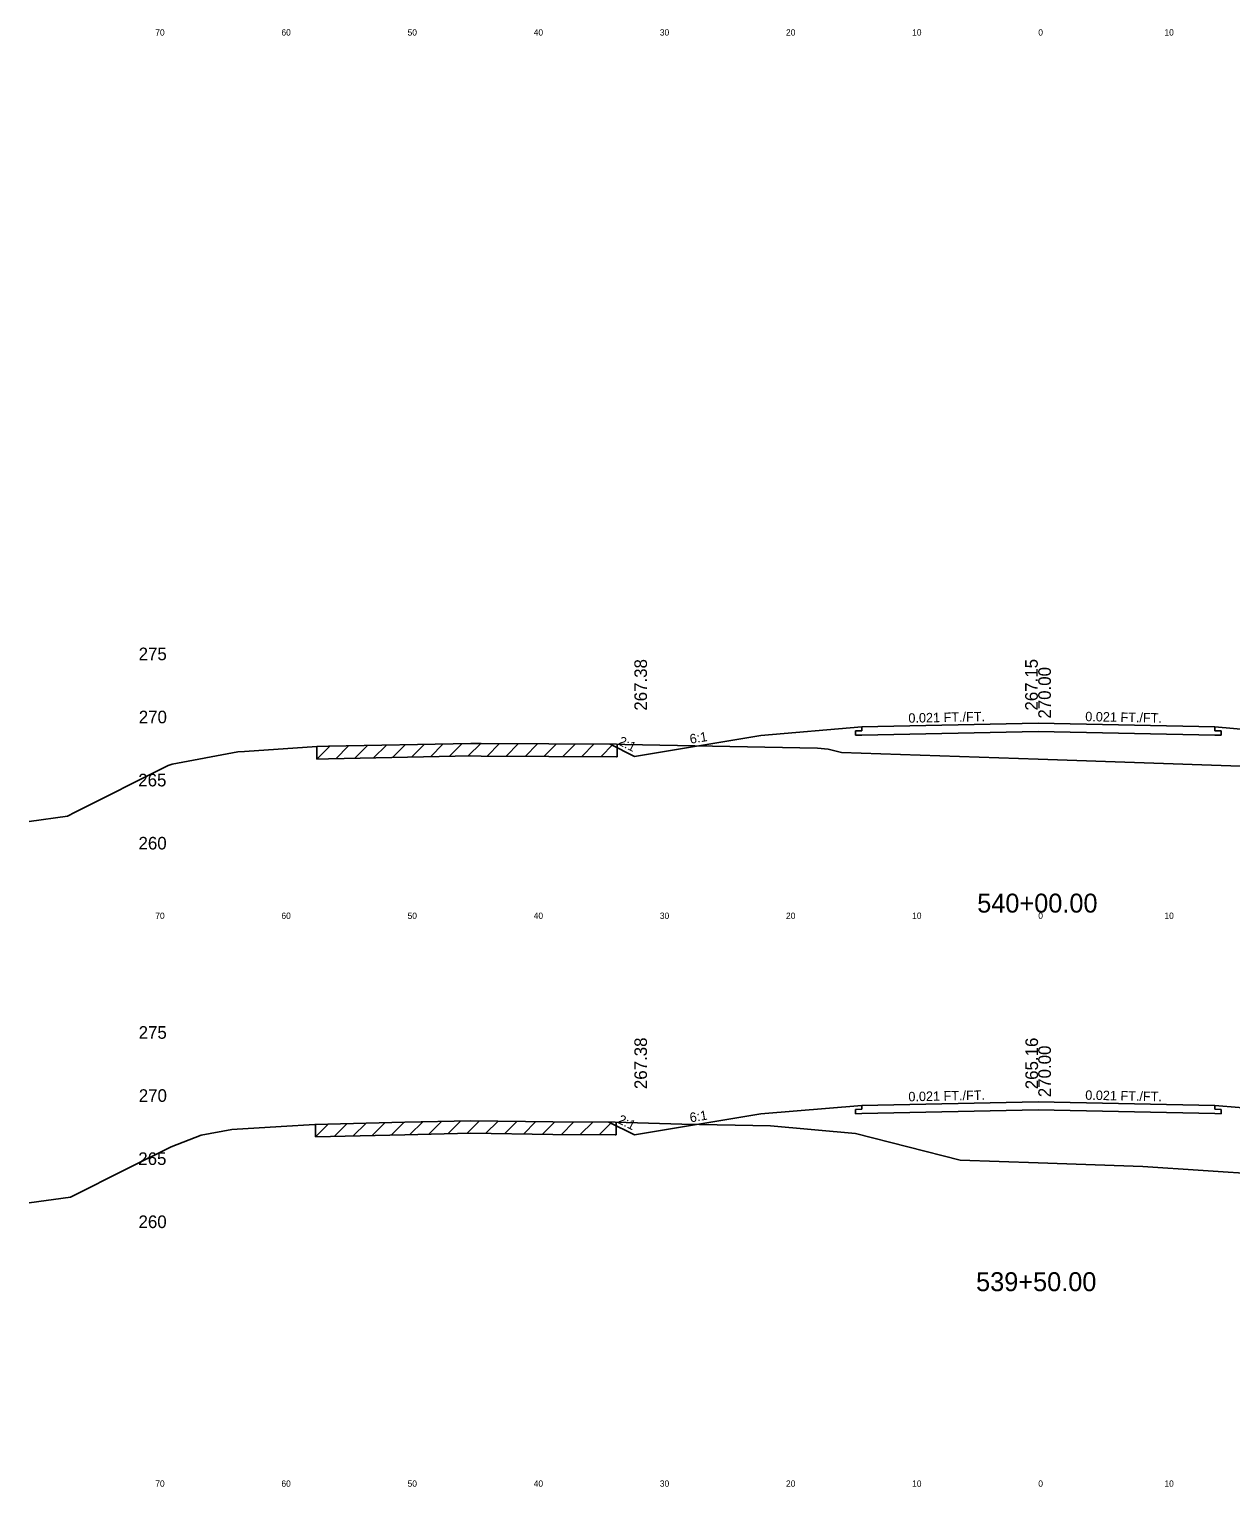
# Model space of a CAD drawing. Extents: x 1000 to 1162, y 999 to 8520.
# Drawn here: x 1000 to 1095.3, y 6059.5 to 6175 of the extents above; entities that cross this region are included whole.
import ezdxf

# ---------------------------------------------------------------- set-up
doc = ezdxf.new("R2010")
doc.units = 0
for name, color, linetype in [('Level 10', 7, 'Continuous'), ('Level 11', 7, 'Continuous'), ('Level 12', 7, 'Continuous'), ('Level 3', 7, 'Continuous'), ('Level 32', 7, 'Continuous'), ('Level 33', 7, 'Continuous'), ('Level 56', 7, 'Continuous'), ('Level 59', 7, 'Continuous'), ('Level 6', 7, 'Continuous'), ('Level 60', 7, 'Continuous'), ('Level 61', 7, 'Continuous'), ('Level 7', 7, 'Continuous')]:
    doc.layers.add(name, color=color, linetype=linetype)

msp = doc.modelspace()

# ---------------------------------------------------------------- linework, layer by layer
at = {"layer": 'Level 11'}
for p, q in [((1066, 6119.41), (1065.5, 6119.4)), ((1065.5, 6119.4), (1065.5, 6119.06)), ((1065.5, 6119.06), (1066, 6119.07)), ((1066, 6119.71), (1066, 6119.41)), ((1094, 6119.41), (1094, 6119.71)), ((1094.5, 6119.4), (1094, 6119.41)), ((1094, 6119.07), (1094.5, 6119.06)), ((1094.5, 6119.06), (1094.5, 6119.4)), ((1066, 6089.41), (1065.5, 6089.4)), ((1065.5, 6089.4), (1065.5, 6089.06)), ((1065.5, 6089.06), (1066, 6089.07)), ((1066, 6089.71), (1066, 6089.41)), ((1094, 6089.41), (1094, 6089.71)), ((1094.5, 6089.4), (1094, 6089.41)), ((1094, 6089.07), (1094.5, 6089.06)), ((1094.5, 6089.06), (1094.5, 6089.4))]:
    msp.add_line(p, q, dxfattribs=at)
at = {"layer": 'Level 12'}
for p, q in [((1080, 6119.36), (1066, 6119.07)), ((1094, 6119.07), (1080, 6119.36)), ((1080, 6089.36), (1066, 6089.07)), ((1094, 6089.07), (1080, 6089.36))]:
    msp.add_line(p, q, dxfattribs=at)
at = {"layer": 'Level 59'}
for p, q in [((1066, 6119.71), (1080, 6120)), ((1080, 6120), (1094, 6119.71)), ((1066, 6089.71), (1080, 6090)), ((1080, 6090), (1094, 6089.71))]:
    msp.add_line(p, q, dxfattribs=at)
at = {"layer": 'Level 6'}
for p, q in [((1058, 6119.04), (1066, 6119.71)), ((1094, 6119.71), (1102, 6119.04)), ((1058, 6089.04), (1066, 6089.71)), ((1094, 6089.71), (1102, 6089.04))]:
    msp.add_line(p, q, dxfattribs=at)
at = {"layer": 'Level 60'}
for p, q in [((1011.35, 6116.77), (1016.55, 6117.74)), ((1016.55, 6117.74), (1017.06, 6117.77)), ((1017.06, 6117.77), (1022.8, 6118.16)), ((1022.8, 6118.16), (1023.72, 6118.18)), ((1023.72, 6118.18), (1035.02, 6118.41)), ((1035.02, 6118.41), (1035.84, 6118.4)), ((1035.84, 6118.4), (1046.56, 6118.35)), ((1046.56, 6118.35), (1047.23, 6118.33)), ((1047.23, 6118.33), (1062.49, 6118.03)), ((1062.49, 6118.03), (1063.34, 6117.95)), ((1063.34, 6117.95), (1064.39, 6117.68)), ((1064.39, 6117.68), (1080, 6117.15)), ((1003.66, 6112.96), (1011.03, 6116.65)), ((1011.03, 6116.65), (1011.35, 6116.77)), ((1080, 6117.15), (1096.03, 6116.61)), ((1000, 6112.23), (1003.04, 6112.65)), ((1003.04, 6112.65), (1003.66, 6112.96)), ((1013.65, 6087.35), (1016.07, 6087.8)), ((1016.07, 6087.8), (1019.97, 6088.04)), ((1019.97, 6088.04), (1022.64, 6088.22)), ((1022.64, 6088.22), (1029.78, 6088.4)), ((1029.78, 6088.4), (1035, 6088.51)), ((1035, 6088.51), (1041.52, 6088.42)), ((1041.52, 6088.42), (1046.45, 6088.39)), ((1046.45, 6088.39), (1051.75, 6088.23)), ((1051.75, 6088.23), (1058.76, 6088.09)), ((1058.76, 6088.09), (1065.51, 6087.49)), ((1011.25, 6086.44), (1013.65, 6087.35)), ((1065.51, 6087.49), (1073.82, 6085.37)), ((1007.8, 6084.71), (1011.25, 6086.44)), ((1073.82, 6085.37), (1080, 6085.16)), ((1003.29, 6082.44), (1007.8, 6084.71)), ((1080, 6085.16), (1088.3, 6084.87)), ((1088.3, 6084.87), (1102.05, 6083.96)), ((1000, 6081.99), (1003.29, 6082.44))]:
    msp.add_line(p, q, dxfattribs=at)
at = {"layer": 'Level 61'}
for p, q in [((1023.83, 6118.18), (1022.81, 6117.16)), ((1022.81, 6118.16), (1022.81, 6117.16)), ((1025.33, 6118.22), (1024.31, 6117.19)), ((1026.83, 6118.25), (1025.81, 6117.23)), ((1028.33, 6118.28), (1027.31, 6117.26)), ((1029.83, 6118.31), (1028.81, 6117.29)), ((1031.33, 6118.34), (1030.31, 6117.32)), ((1032.83, 6118.37), (1031.81, 6117.35)), ((1034.33, 6118.4), (1033.31, 6117.38)), ((1035.8, 6118.4), (1034.81, 6117.41)), ((1037.3, 6118.39), (1036.31, 6117.4)), ((1038.8, 6118.39), (1037.81, 6117.39)), ((1040.3, 6118.38), (1039.31, 6117.38)), ((1041.8, 6118.37), (1040.81, 6117.38)), ((1043.3, 6118.36), (1042.31, 6117.37)), ((1044.8, 6118.36), (1043.81, 6117.36)), ((1046.3, 6118.35), (1045.31, 6117.35)), ((1046.61, 6117.35), (1046.61, 6118.35)), ((1022.81, 6117.16), (1023.72, 6117.18)), ((1023.72, 6117.18), (1035.02, 6117.41)), ((1035.02, 6117.41), (1035.84, 6117.4)), ((1035.84, 6117.4), (1046.56, 6117.35)), ((1046.56, 6117.35), (1046.61, 6117.35)), ((1023.72, 6088.25), (1022.69, 6087.22)), ((1022.69, 6088.22), (1022.69, 6087.22)), ((1025.22, 6088.28), (1024.19, 6087.26)), ((1026.72, 6088.32), (1025.69, 6087.3)), ((1028.22, 6088.36), (1027.19, 6087.34)), ((1029.72, 6088.4), (1028.69, 6087.37)), ((1031.21, 6088.43), (1030.19, 6087.41)), ((1032.71, 6088.46), (1031.69, 6087.44)), ((1034.21, 6088.49), (1033.19, 6087.47)), ((1035.69, 6088.5), (1034.69, 6087.5)), ((1037.18, 6088.48), (1036.19, 6087.49)), ((1038.68, 6088.46), (1037.69, 6087.47)), ((1040.18, 6088.44), (1039.19, 6087.45)), ((1041.68, 6088.42), (1040.69, 6087.43)), ((1043.19, 6088.41), (1042.19, 6087.41)), ((1044.69, 6088.4), (1043.69, 6087.41)), ((1046.19, 6088.39), (1045.19, 6087.4)), ((1046.55, 6087.39), (1046.55, 6088.39)), ((1022.69, 6087.22), (1029.78, 6087.4)), ((1029.78, 6087.4), (1035, 6087.51)), ((1035, 6087.51), (1041.52, 6087.42)), ((1041.52, 6087.42), (1046.45, 6087.39)), ((1046.45, 6087.39), (1046.55, 6087.39))]:
    msp.add_line(p, q, dxfattribs=at)
at = {"layer": 'Level 7'}
for p, q in [((1048, 6117.38), (1058, 6119.04)), ((1046.05, 6118.35), (1048, 6117.38)), ((1048, 6087.38), (1058, 6089.04)), ((1045.96, 6088.39), (1048, 6087.38))]:
    msp.add_line(p, q, dxfattribs=at)

# ---------------------------------------------------------------- texts
at = {"layer": 'Level 10'}
for s, p in [('267.15', (1079.96, 6121.01)), ('265.16', (1079.98, 6091))]:
    msp.add_text(s, height=1, rotation=90, dxfattribs=at).set_placement(p)
at = {"layer": 'Level 11'}
for s, p in [(' 275', (1008.31, 6125)), (' 270', (1008.32, 6120)), (' 265', (1008.28, 6115)), (' 260', (1008.3, 6110)), (' 275', (1008.31, 6095)), (' 270', (1008.32, 6090)), (' 265', (1008.28, 6085)), (' 260', (1008.3, 6080))]:
    msp.add_text(s, height=1, dxfattribs=at).set_placement(p)
at = {"layer": 'Level 3'}
for s, p in [('540+00.00', (1075.16, 6105)), ('539+50.00', (1075.07, 6075))]:
    msp.add_text(s, height=1.5, dxfattribs=at).set_placement(p)
at = {"layer": 'Level 32'}
for s, rotation, p in [('0.021 FT./FT.', 1.1916, (1069.71, 6120.04)), ('0.021 FT./FT.', 358.8084, (1083.72, 6120.17)), ('2:1', 333.435, (1046.63, 6118.34)), ('6:1', 9.4623, (1052.43, 6118.37)), ('0.021 FT./FT.', 1.1916, (1069.71, 6090.04)), ('0.021 FT./FT.', 358.8084, (1083.72, 6090.17)), ('2:1', 333.435, (1046.59, 6088.36)), ('6:1', 9.4623, (1052.43, 6088.37))]:
    msp.add_text(s, height=0.75, rotation=rotation, dxfattribs=at).set_placement(p)
at = {"layer": 'Level 33'}
for p in [(1048.98, 6121), (1048.98, 6091.01)]:
    msp.add_text('267.38', height=1, rotation=90, dxfattribs=at).set_placement(p)
at = {"layer": 'Level 56'}
for s, p in [('70', (1010, 6174.5)), ('60', (1020, 6174.5)), ('50', (1030, 6174.5)), ('40', (1040, 6174.5)), ('30', (1050, 6174.5)), ('20', (1060, 6174.5)), ('10', (1070, 6174.5)), ('0', (1080, 6174.5)), ('10', (1090, 6174.5)), ('70', (1010, 6104.5)), ('60', (1020, 6104.5)), ('50', (1030, 6104.5)), ('40', (1040, 6104.5)), ('30', (1050, 6104.5)), ('20', (1060, 6104.5)), ('10', (1070, 6104.5)), ('0', (1080, 6104.5)), ('10', (1090, 6104.5)), ('70', (1010, 6059.5)), ('60', (1020, 6059.5)), ('50', (1030, 6059.5)), ('40', (1040, 6059.5)), ('30', (1050, 6059.5)), ('20', (1060, 6059.5)), ('10', (1070, 6059.5)), ('0', (1080, 6059.5)), ('10', (1090, 6059.5))]:
    msp.add_text(s, height=0.5, dxfattribs=at).set_placement(p)
at = {"layer": 'Level 59'}
for p in [(1081, 6120), (1081, 6090)]:
    msp.add_text(' 270.00', height=1, rotation=90, dxfattribs=at).set_placement(p)

doc.saveas('drawing.dxf')
